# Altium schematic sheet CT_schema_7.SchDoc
size 371 x 245 mm
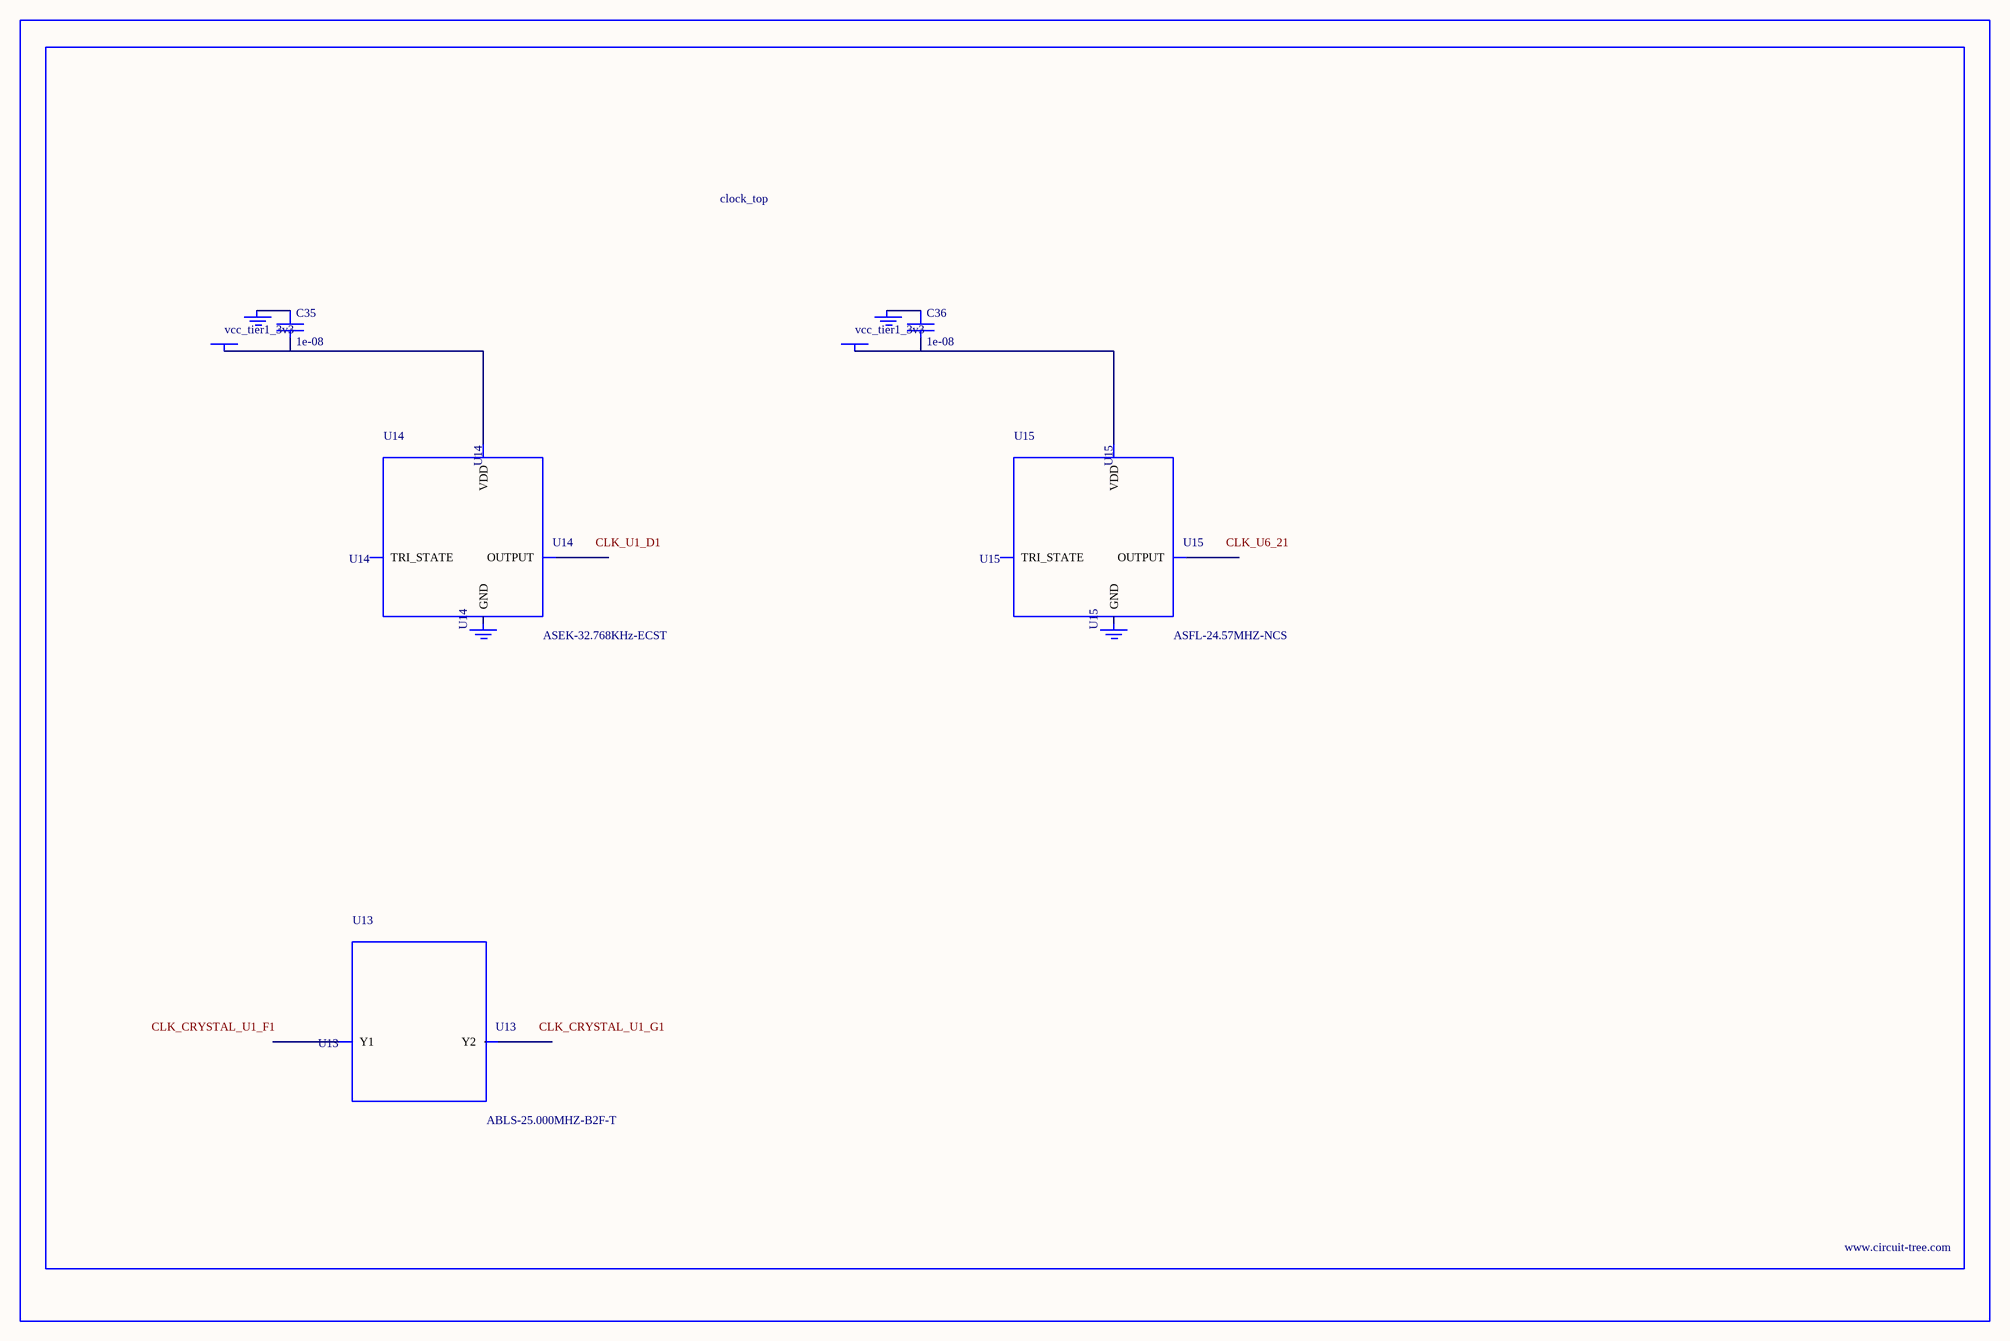
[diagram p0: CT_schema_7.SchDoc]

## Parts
BORDER6  (no value)
C35  1e-08  [C0402]
C36  1e-08  [C0402]
GND_INSTANCE_6_0  (no value)
GND_INSTANCE_6_1  (no value)
GND_INSTANCE_6_2  (no value)
GND_INSTANCE_6_3  (no value)
POWER_INSTANCE_6_0  vcc_tier1_3v3
POWER_INSTANCE_6_1  vcc_tier1_3v3
U13  ABLS-25.000MHZ-B2F-T  [ABLS-25.000MHZ-B2F-T]
U14  ASEK-32.768KHz-ECST  [ASEK]
U15  ASFL-24.57MHZ-NCS  [ASFL1]

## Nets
NetC35_1: C35.1 GND_INSTANCE_6_0.0(GND)
NetC35_2: C35.2 POWER_INSTANCE_6_0.0(PWR) U14.4(VDD)
NetC36_1: C36.1 GND_INSTANCE_6_2.0(GND)
NetC36_2: C36.2 POWER_INSTANCE_6_1.0(PWR) U15.4(VDD)

Not connected (* = marked no-connect by the designer): GND_INSTANCE_6_1 0(GND); GND_INSTANCE_6_3 0(GND); U13 1(Y1) 2(Y2); U14 1(TRI_STATE) 2(GND) 3(OUTPUT); U15 1(TRI_STATE) 2(GND) 3(OUTPUT)

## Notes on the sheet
- Labels drawn without touching a wire or pin: CLK_CRYSTAL_U1_F1, CLK_CRYSTAL_U1_G1, CLK_U1_D1, CLK_U6_21

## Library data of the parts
BORDER6 = BORDER_PAGE6
C35 C36 = C0402C103K3RAC
GND_INSTANCE_6_0-GND_INSTANCE_6_3 = GND
POWER_INSTANCE_6_0 POWER_INSTANCE_6_1 = PWR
